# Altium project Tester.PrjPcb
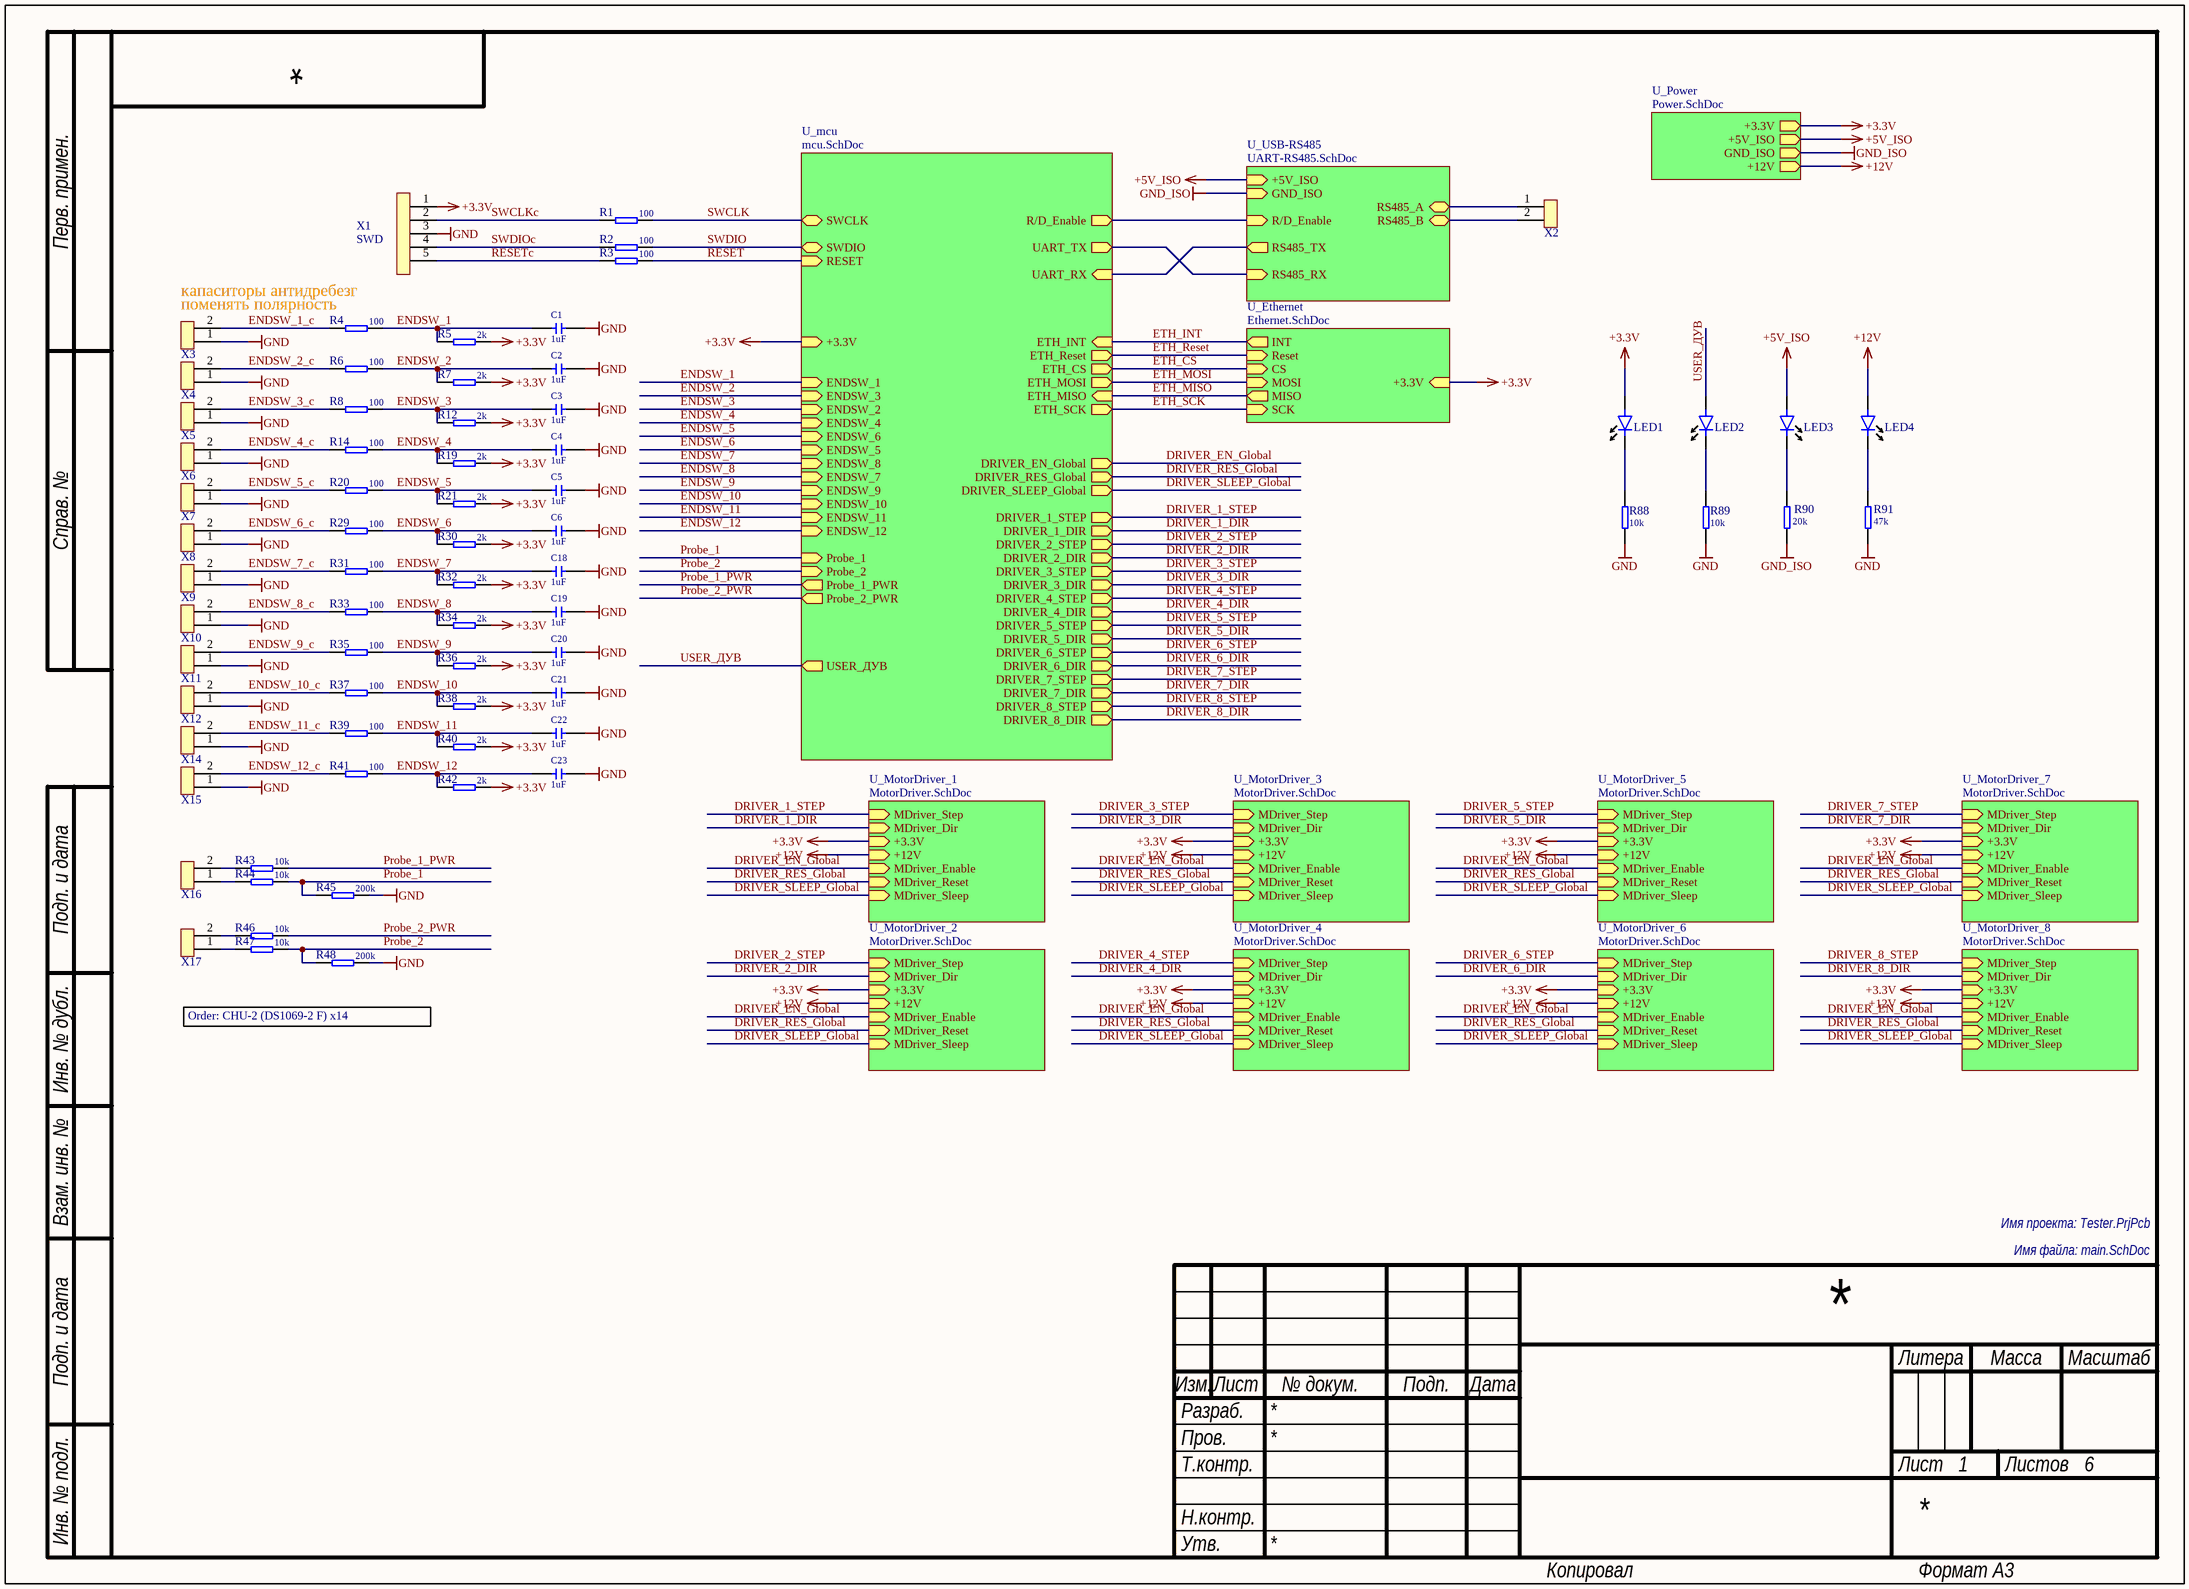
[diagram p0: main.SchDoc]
6 sheets, 275 parts. Net scope: hierarchical (ports join the sheet entries above them; power ports are global).
Sheets:
  main.SchDoc
    U_mcu = mcu.SchDoc
    U_Ethernet = Ethernet.SchDoc
    U_USB-RS485 = UART-RS485.SchDoc
    U_MotorDriver_1 = MotorDriver.SchDoc
    U_Power = Power.SchDoc
    U_MotorDriver_2 = MotorDriver.SchDoc
    U_MotorDriver_3 = MotorDriver.SchDoc
    U_MotorDriver_4 = MotorDriver.SchDoc
    U_MotorDriver_5 = MotorDriver.SchDoc
    U_MotorDriver_6 = MotorDriver.SchDoc
    U_MotorDriver_7 = MotorDriver.SchDoc
    U_MotorDriver_8 = MotorDriver.SchDoc

## Sheet main.SchDoc
size 410 x 297 mm; SheetNumber: 1; SheetTotal: 6

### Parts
Additional_order2  Order: CHU-2 (DS1069-2 F) x14  (hidden comment: Additional order)  (mechanical)
C1  1uF  [CERCAP 0603]
C2  1uF  [CERCAP 0603]
C3  1uF  [CERCAP 0603]
C4  1uF  [CERCAP 0603]
C5  1uF  [CERCAP 0603]
C6  1uF  [CERCAP 0603]
C18  1uF  [CERCAP 0603]
C19  1uF  [CERCAP 0603]
C20  1uF  [CERCAP 0603]
C21  1uF  [CERCAP 0603]
C22  1uF  [CERCAP 0603]
C23  1uF  [CERCAP 0603]
LED1  LED  [LED-0603N]  (value not drawn)
LED2  LED  [LED-0603N]  (value not drawn)
LED3  ***LED WHITE***  [LED-0603N]  (value not drawn)
LED4  ***LED WHITE***  [LED-0603N]  (value not drawn)
R1  100  [RES 0603]
R2  100  [RES 0603]
R3  100  [RES 0603]
R4  100  [RES 0603]
R5  2k  [RES 0603]
R6  100  [RES 0603]
R7  2k  [RES 0603]
R8  100  [RES 0603]
R12  2k  [RES 0603]
R14  100  [RES 0603]
R19  2k  [RES 0603]
R20  100  [RES 0603]
R21  2k  [RES 0603]
R29  100  [RES 0603]
R30  2k  [RES 0603]
R31  100  [RES 0603]
R32  2k  [RES 0603]
R33  100  [RES 0603]
R34  2k  [RES 0603]
R35  100  [RES 0603]
R36  2k  [RES 0603]
R37  100  [RES 0603]
R38  2k  [RES 0603]
R39  100  [RES 0603]
R40  2k  [RES 0603]
R41  100  [RES 0603]
R42  2k  [RES 0603]
R43  10k  [RES 0603]
R44  10k  [RES 0603]
R45  200k  [RES 0603]
R46  10k  [RES 0603]
R47  10k  [RES 0603]
R48  200k  [RES 0603]
R88  10k  [RES 0603]
R89  10k  [RES 0603]
R90  value 20k  [RES 0603]
R91  value 47k  [RES 0603]
X1  SWD  [PLS-5-2.54]
X2  Header  [CWF-2]  (value not drawn)
X3  Header  [CWF-2]  (value not drawn)
X4  Header  [CWF-2]  (value not drawn)
X5  Header  [CWF-2]  (value not drawn)
X6  Header  [CWF-2]  (value not drawn)
X7  Header  [CWF-2]  (value not drawn)
X8  Header  [CWF-2]  (value not drawn)
X9  Header  [CWF-2]  (value not drawn)
X10  Header  [CWF-2]  (value not drawn)
X11  Header  [CWF-2]  (value not drawn)
X12  Header  [CWF-2]  (value not drawn)
X14  Header  [CWF-2]  (value not drawn)
X15  Header  [CWF-2]  (value not drawn)
X16  Header  [CWF-2]  (value not drawn)
X17  Header  [CWF-2]  (value not drawn)

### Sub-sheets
U_Ethernet = Ethernet.SchDoc: +3.3V (in), Reset (in), CS (in), MOSI (in), MISO (out), SCK (in), INT (out)
U_mcu = mcu.SchDoc: UART_TX (out), UART_RX (in), SWCLK (bidir), SWDIO (bidir), RESET (in), +3.3V (in), ETH_INT (in), ETH_Reset (out), ETH_CS (out), ETH_MOSI (out), ETH_MISO (in), ETH_SCK (out), ENDSW_1 (in), ENDSW_2 (in), ENDSW_3 (in), ENDSW_4 (in), ENDSW_5 (in), ENDSW_6 (in), ENDSW_7 (in), ENDSW_8 (in), ENDSW_9 (in), ENDSW_10 (in), R/D_Enable (out), ENDSW_11 (in), ENDSW_12 (in), Probe_1 (in), Probe_2 (in), DRIVER_EN_Global (out), DRIVER_RES_Global (out), DRIVER_SLEEP_Global (out), DRIVER_1_STEP (out), DRIVER_1_DIR (out), DRIVER_2_STEP (out), DRIVER_2_DIR (out), DRIVER_3_STEP (out), DRIVER_3_DIR (out), DRIVER_4_STEP (out), DRIVER_4_DIR (out), DRIVER_5_STEP (out), DRIVER_5_DIR (out), DRIVER_6_STEP (out), DRIVER_6_DIR (out), DRIVER_7_STEP (out), DRIVER_7_DIR (out), DRIVER_8_STEP (out), DRIVER_8_DIR (out), Probe_1_PWR (out), Probe_2_PWR (out), USER_ДУВ (out)
U_MotorDriver_1 = MotorDriver.SchDoc: MDriver_Step (in), MDriver_Dir (in), +3.3V (in), +12V (in), MDriver_Enable (in), MDriver_Reset (in), MDriver_Sleep (in)
U_MotorDriver_2 = MotorDriver.SchDoc: MDriver_Step (in), MDriver_Dir (in), +3.3V (in), +12V (in), MDriver_Enable (in), MDriver_Reset (in), MDriver_Sleep (in)
U_MotorDriver_3 = MotorDriver.SchDoc: MDriver_Step (in), MDriver_Dir (in), +3.3V (in), +12V (in), MDriver_Enable (in), MDriver_Reset (in), MDriver_Sleep (in)
U_MotorDriver_4 = MotorDriver.SchDoc: MDriver_Step (in), MDriver_Dir (in), +3.3V (in), +12V (in), MDriver_Enable (in), MDriver_Reset (in), MDriver_Sleep (in)
U_MotorDriver_5 = MotorDriver.SchDoc: MDriver_Step (in), MDriver_Dir (in), +3.3V (in), +12V (in), MDriver_Enable (in), MDriver_Reset (in), MDriver_Sleep (in)
U_MotorDriver_6 = MotorDriver.SchDoc: MDriver_Step (in), MDriver_Dir (in), +3.3V (in), +12V (in), MDriver_Enable (in), MDriver_Reset (in), MDriver_Sleep (in)
U_MotorDriver_7 = MotorDriver.SchDoc: MDriver_Step (in), MDriver_Dir (in), +3.3V (in), +12V (in), MDriver_Enable (in), MDriver_Reset (in), MDriver_Sleep (in)
U_MotorDriver_8 = MotorDriver.SchDoc: MDriver_Step (in), MDriver_Dir (in), +3.3V (in), +12V (in), MDriver_Enable (in), MDriver_Reset (in), MDriver_Sleep (in)
U_Power = Power.SchDoc: +5V_ISO (out), GND_ISO (out), +12V (out), +3.3V (out)
U_USB-RS485 = UART-RS485.SchDoc: RS485_RX (in), RS485_TX (out), GND_ISO (in), +5V_ISO (in), R/D_Enable (in), RS485_A (bidir), RS485_B (bidir)

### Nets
+3.3V: LED1.1(Anode) R5.2 R7.2 R12.2 R19.2 R21.2 R30.2 R32.2 R34.2 R36.2 R38.2 R40.2 R42.2 X1.1 ; sheet U_mcu/+3.3V, sheet U_Ethernet/+3.3V, sheet U_MotorDriver_1/+3.3V, sheet U_Power/+3.3V, sheet U_MotorDriver_2/+3.3V, sheet U_MotorDriver_3/+3.3V, sheet U_MotorDriver_4/+3.3V, sheet U_MotorDriver_5/+3.3V, sheet U_MotorDriver_6/+3.3V, sheet U_MotorDriver_7/+3.3V, sheet U_MotorDriver_8/+3.3V
+5V_ISO: LED3.1(Anode) ; sheet U_USB-RS485/+5V_ISO, sheet U_Power/+5V_ISO
+12V: LED4.1(Anode) ; sheet U_MotorDriver_1/+12V, sheet U_Power/+12V, sheet U_MotorDriver_2/+12V, sheet U_MotorDriver_3/+12V, sheet U_MotorDriver_4/+12V, sheet U_MotorDriver_5/+12V, sheet U_MotorDriver_6/+12V, sheet U_MotorDriver_7/+12V, sheet U_MotorDriver_8/+12V
GND: C1.2 C2.2 C3.2 C4.2 C5.2 C6.2 C18.2 C19.2 C20.2 C21.2 C22.2 C23.2 R45.2 R48.2 R88.2 R89.2 R91.2 X1.3 X3.1 X4.1 X5.1 X6.1 X7.1 X8.1 X9.1 X10.1 X11.1 X12.1 X14.1 X15.1
GND_ISO: R90.2 ; sheet U_USB-RS485/GND_ISO, sheet U_Power/GND_ISO
DRIVER_1_DIR: sheet U_mcu/DRIVER_1_DIR, sheet U_MotorDriver_1/MDriver_Dir
DRIVER_1_STEP: sheet U_mcu/DRIVER_1_STEP, sheet U_MotorDriver_1/MDriver_Step
DRIVER_2_DIR: sheet U_mcu/DRIVER_2_DIR, sheet U_MotorDriver_2/MDriver_Dir
DRIVER_2_STEP: sheet U_mcu/DRIVER_2_STEP, sheet U_MotorDriver_2/MDriver_Step
DRIVER_3_DIR: sheet U_mcu/DRIVER_3_DIR, sheet U_MotorDriver_3/MDriver_Dir
DRIVER_3_STEP: sheet U_mcu/DRIVER_3_STEP, sheet U_MotorDriver_3/MDriver_Step
DRIVER_4_DIR: sheet U_mcu/DRIVER_4_DIR, sheet U_MotorDriver_4/MDriver_Dir
DRIVER_4_STEP: sheet U_mcu/DRIVER_4_STEP, sheet U_MotorDriver_4/MDriver_Step
DRIVER_5_DIR: sheet U_mcu/DRIVER_5_DIR, sheet U_MotorDriver_5/MDriver_Dir
DRIVER_5_STEP: sheet U_mcu/DRIVER_5_STEP, sheet U_MotorDriver_5/MDriver_Step
DRIVER_6_DIR: sheet U_mcu/DRIVER_6_DIR, sheet U_MotorDriver_6/MDriver_Dir
DRIVER_6_STEP: sheet U_mcu/DRIVER_6_STEP, sheet U_MotorDriver_6/MDriver_Step
DRIVER_7_DIR: sheet U_mcu/DRIVER_7_DIR, sheet U_MotorDriver_7/MDriver_Dir
DRIVER_7_STEP: sheet U_mcu/DRIVER_7_STEP, sheet U_MotorDriver_7/MDriver_Step
DRIVER_8_DIR: sheet U_mcu/DRIVER_8_DIR, sheet U_MotorDriver_8/MDriver_Dir
DRIVER_8_STEP: sheet U_mcu/DRIVER_8_STEP, sheet U_MotorDriver_8/MDriver_Step
DRIVER_EN_Global: sheet U_mcu/DRIVER_EN_Global, sheet U_MotorDriver_1/MDriver_Enable, sheet U_MotorDriver_2/MDriver_Enable, sheet U_MotorDriver_3/MDriver_Enable, sheet U_MotorDriver_4/MDriver_Enable, sheet U_MotorDriver_5/MDriver_Enable, sheet U_MotorDriver_6/MDriver_Enable, sheet U_MotorDriver_7/MDriver_Enable, sheet U_MotorDriver_8/MDriver_Enable
DRIVER_RES_Global: sheet U_mcu/DRIVER_RES_Global, sheet U_MotorDriver_1/MDriver_Reset, sheet U_MotorDriver_2/MDriver_Reset, sheet U_MotorDriver_3/MDriver_Reset, sheet U_MotorDriver_4/MDriver_Reset, sheet U_MotorDriver_5/MDriver_Reset, sheet U_MotorDriver_6/MDriver_Reset, sheet U_MotorDriver_7/MDriver_Reset, sheet U_MotorDriver_8/MDriver_Reset
DRIVER_SLEEP_Global: sheet U_mcu/DRIVER_SLEEP_Global, sheet U_MotorDriver_1/MDriver_Sleep, sheet U_MotorDriver_2/MDriver_Sleep, sheet U_MotorDriver_3/MDriver_Sleep, sheet U_MotorDriver_4/MDriver_Sleep, sheet U_MotorDriver_5/MDriver_Sleep, sheet U_MotorDriver_6/MDriver_Sleep, sheet U_MotorDriver_7/MDriver_Sleep, sheet U_MotorDriver_8/MDriver_Sleep
ENDSW_1: C1.1 R4.2 R5.1 ; sheet U_mcu/ENDSW_1
ENDSW_1_c: R4.1 X3.2
ENDSW_2: C2.1 R6.2 R7.1 ; sheet U_mcu/ENDSW_3
ENDSW_2_c: R6.1 X4.2
ENDSW_3: C3.1 R8.2 R12.1 ; sheet U_mcu/ENDSW_2
ENDSW_3_c: R8.1 X5.2
ENDSW_4: C4.1 R14.2 R19.1 ; sheet U_mcu/ENDSW_4
ENDSW_4_c: R14.1 X6.2
ENDSW_5: C5.1 R20.2 R21.1 ; sheet U_mcu/ENDSW_6
ENDSW_5_c: R20.1 X7.2
ENDSW_6: C6.1 R29.2 R30.1 ; sheet U_mcu/ENDSW_5
ENDSW_6_c: R29.1 X8.2
ENDSW_7: C18.1 R31.2 R32.1 ; sheet U_mcu/ENDSW_8
ENDSW_7_c: R31.1 X9.2
ENDSW_8: C19.1 R33.2 R34.1 ; sheet U_mcu/ENDSW_7
ENDSW_8_c: R33.1 X10.2
ENDSW_9: C20.1 R35.2 R36.1 ; sheet U_mcu/ENDSW_9
ENDSW_9_c: R35.1 X11.2
ENDSW_10: C21.1 R37.2 R38.1 ; sheet U_mcu/ENDSW_10
ENDSW_10_c: R37.1 X12.2
ENDSW_11: C22.1 R39.2 R40.1 ; sheet U_mcu/ENDSW_11
ENDSW_11_c: R39.1 X14.2
ENDSW_12: C23.1 R41.2 R42.1 ; sheet U_mcu/ENDSW_12
ENDSW_12_c: R41.1 X15.2
ETH_CS: sheet U_mcu/ETH_CS, sheet U_Ethernet/CS
ETH_INT: sheet U_mcu/ETH_INT, sheet U_Ethernet/INT
ETH_MISO: sheet U_mcu/ETH_MISO, sheet U_Ethernet/MISO
ETH_MOSI: sheet U_mcu/ETH_MOSI, sheet U_Ethernet/MOSI
ETH_Reset: sheet U_mcu/ETH_Reset, sheet U_Ethernet/Reset
ETH_SCK: sheet U_mcu/ETH_SCK, sheet U_Ethernet/SCK
Probe_1: R44.2 R45.1 ; sheet U_mcu/Probe_1
Probe_1_PWR: R43.2 ; sheet U_mcu/Probe_1_PWR
Probe_2: R47.2 R48.1 ; sheet U_mcu/Probe_2
Probe_2_PWR: R46.2 ; sheet U_mcu/Probe_2_PWR
RESET: R3.2 ; sheet U_mcu/RESET
RESETc: R3.1 X1.5
SWCLK: R1.2 ; sheet U_mcu/SWCLK
SWCLKc: R1.1 X1.2
SWDIO: R2.2 ; sheet U_mcu/SWDIO
SWDIOc: R2.1 X1.4
USER_ДУВ: LED2.1(Anode) ; sheet U_mcu/USER_ДУВ
NetIC1_25: sheet U_mcu/UART_TX, sheet U_USB-RS485/RS485_RX
NetIC1_26: sheet U_mcu/UART_RX, sheet U_USB-RS485/RS485_TX
NetIC1_27: sheet U_mcu/R/D_Enable, sheet U_USB-RS485/R/D_Enable
NetLED1_2: LED1.2(Cathode) R88.1
NetLED2_2: LED2.2(Cathode) R89.1
NetLED3_2: LED3.2(Cathode) R90.1
NetLED4_2: LED4.2(Cathode) R91.1
NetR43_1: R43.1 X16.2
NetR44_1: R44.1 X16.1
NetR46_1: R46.1 X17.2
NetR47_1: R47.1 X17.1
NetR69_1: X2.2 ; sheet U_USB-RS485/RS485_B
NetR69_2: X2.1 ; sheet U_USB-RS485/RS485_A

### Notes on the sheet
- поменять полярность
- капаситоры антидребезг

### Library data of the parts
Additional_order2 = Additional_Order
C1-C6 C18-C23 = cap: Capacitor; Voltage: *V; Dielectric: *X5R; Tolerance: *%; OrderAdvanced: CERCAP *0603 1uF *X5R *%
LED1 LED2 = LED: Light Emittering Diode; PartValue: LED*0603 *; Order: LED 0603 Red; OriginalSource: AltTab
LED3 LED4 = LED: Light Emittering Diode; PartValue: LED*0603 *; OriginalSource: AltTab
R1-R4 R6 R8 R14 R20 R29 R31 R33 R35 R37 R39 R41 = Resistor: OrderAdvanced: RES *0603 100 *%; Tolerance: *%
R5 R7 R12 R19 R21 R30 R32 R34 R36 R38 R40 R42 = Resistor: OrderAdvanced: RES *0603 2k *%; Tolerance: *%
R43 R44 R46 R47 R88 R89 = Resistor: OrderAdvanced: RES *0603 10k *%; Tolerance: *%
R45 R48 = Resistor: OrderAdvanced: RES *0603 200k *%; Tolerance: *%
R90 = Resistor: OrderAdvanced: RES *0603 20k *%; Tolerance: *%
R91 = Resistor: OrderAdvanced: RES *0603 47k *%; Tolerance: *%
X1 = Header 5x1: 5x1 header; Order: 2.54 horizontal 5 contacts SMD; System: Connector; OriginalSource: AltTab
X2 = Header 2x1: 2x1 header; System: Connector; OriginalSource: AltTab
X3-X12 X14-X17 = Header 2x1: 2x1 header; Order: CWF-2 (DS1069-2 M); System: Connector; OriginalSource: AltTab

## Sheet mcu.SchDoc
size A4; SheetNumber: 2; SheetTotal: 6
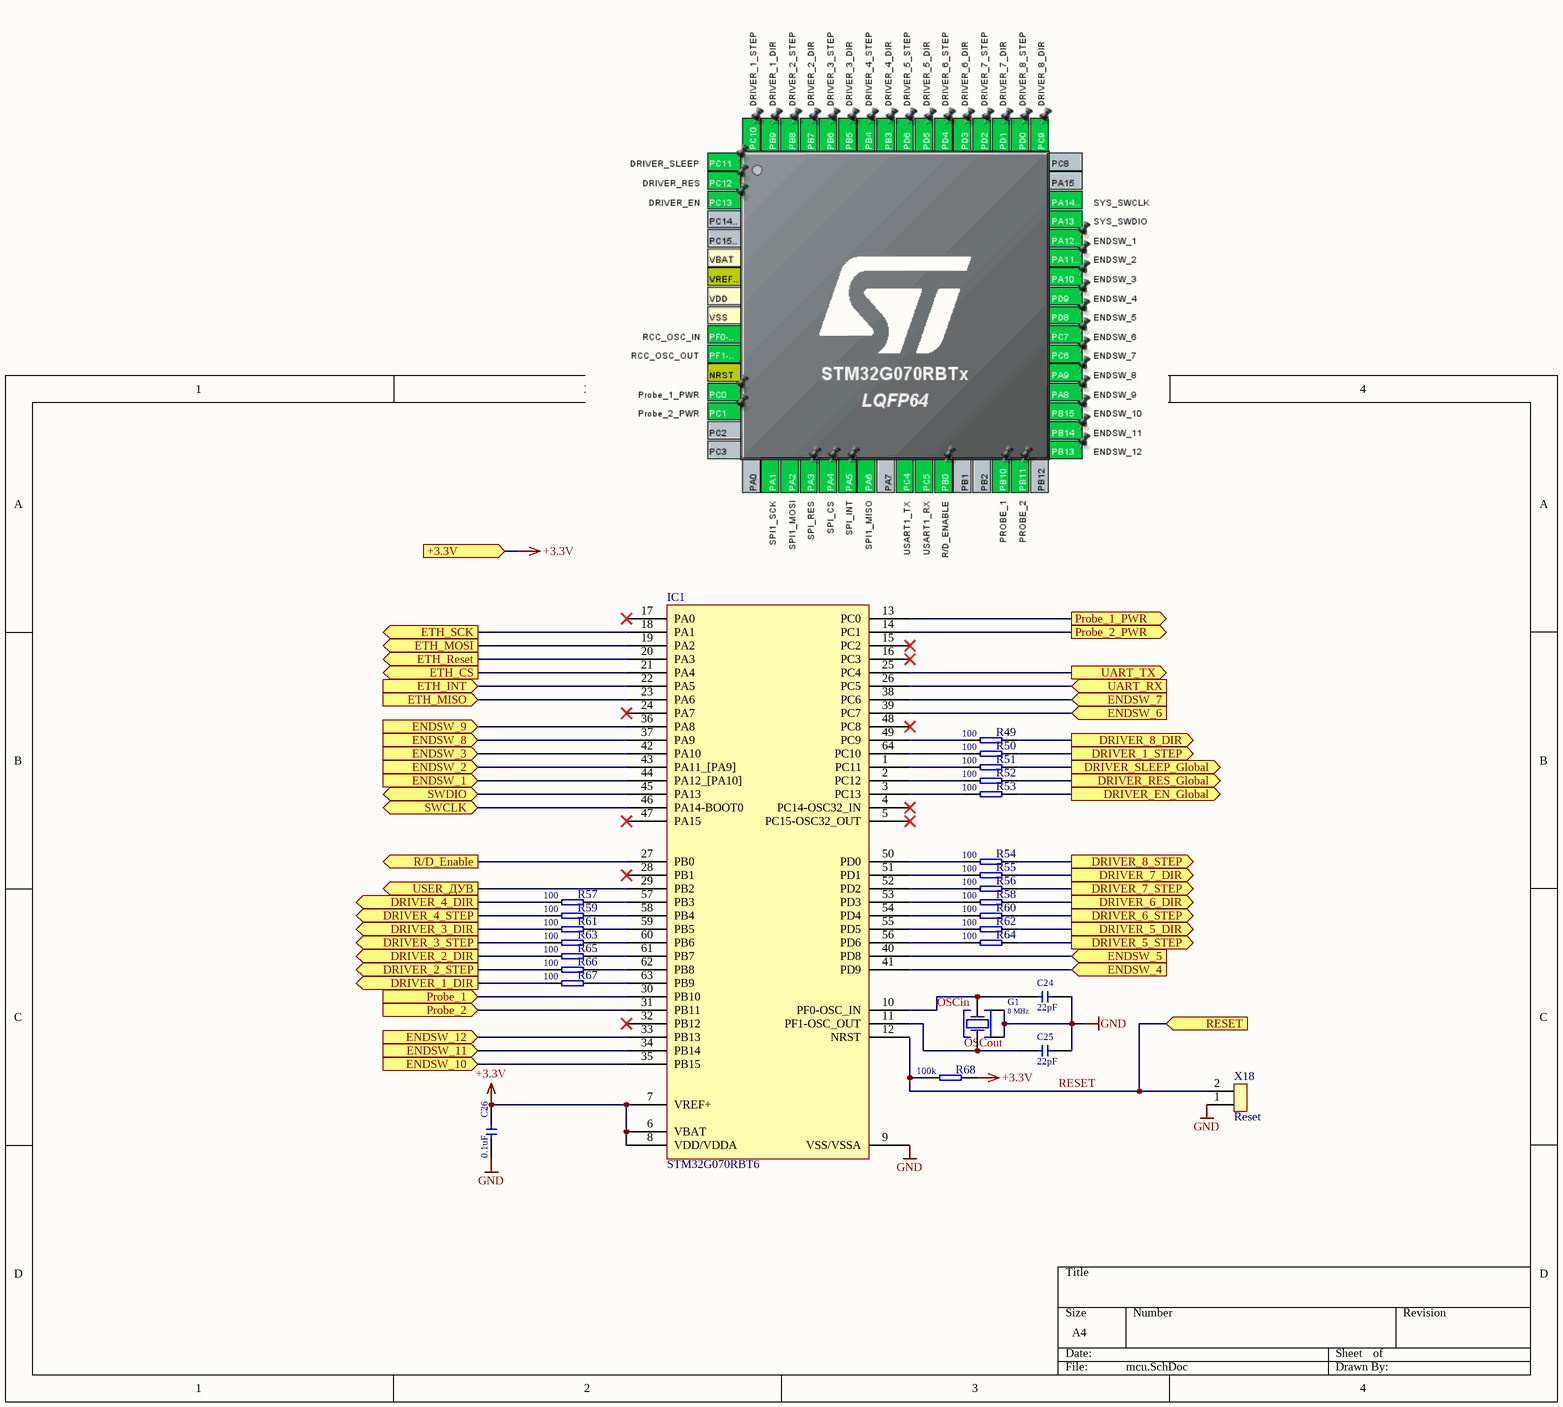
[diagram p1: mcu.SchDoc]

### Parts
C24  22pF  [CERCAP 0603]
C25  22pF  [CERCAP 0603]
C26  0.1uF  [CERCAP 0603]
G1  Frequency: 8 MHz  [SMD_3225_4N]  (hidden comment: Crystal-4)
IC1  STM32G070RBT6  [LQFP-64]
R49  100  [RES-0603N]
R50  100  [RES-0603N]
R51  100  [RES-0603N]
R52  100  [RES-0603N]
R53  100  [RES-0603N]
R54  100  [RES-0603N]
R55  100  [RES-0603N]
R56  100  [RES-0603N]
R57  100  [RES-0603N]
R58  100  [RES-0603N]
R59  100  [RES-0603N]
R60  100  [RES-0603N]
R61  100  [RES-0603N]
R62  100  [RES-0603N]
R63  100  [RES-0603N]
R64  100  [RES-0603N]
R65  100  [RES-0603N]
R66  100  [RES-0603N]
R67  100  [RES-0603N]
R68  100k  [RES-0603N]
X18  Reset  [PLL-2-1.27]

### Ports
+3.3V (in, see main[2A], Ethernet[2A], MotorDriver[3B], Power[3C]), DRIVER_1_DIR (out, see main[3A]), DRIVER_1_STEP (out, see main[3A]), DRIVER_2_DIR (out, see main[3A]), DRIVER_2_STEP (out, see main[3A]), DRIVER_3_DIR (out, see main[3A]), DRIVER_3_STEP (out, see main[3A]), DRIVER_4_DIR (out, see main[3A]), DRIVER_4_STEP (out, see main[3A]), DRIVER_5_DIR (out, see main[3A]), DRIVER_5_STEP (out, see main[3A]), DRIVER_6_DIR (out, see main[3A]), DRIVER_6_STEP (out, see main[3A]), DRIVER_7_DIR (out, see main[3A]), DRIVER_7_STEP (out, see main[3A]), DRIVER_8_DIR (out, see main[3A]), DRIVER_8_STEP (out, see main[3A]), DRIVER_EN_Global (out, see main[3A]), DRIVER_RES_Global (out, see main[3A]), DRIVER_SLEEP_Global (out, see main[3A]), ENDSW_1 (in, see main[2A]), ENDSW_2 (in, see main[2A]), ENDSW_3 (in, see main[2A]), ENDSW_4 (in, see main[2A]), ENDSW_5 (in, see main[2A]), ENDSW_6 (in, see main[2A]), ENDSW_7 (in, see main[2A]), ENDSW_8 (in, see main[2A]), ENDSW_9 (in, see main[2A]), ENDSW_10 (in, see main[2A]), ENDSW_11 (in, see main[2A]), ENDSW_12 (in, see main[2A]), ETH_CS (out, see main[3A]), ETH_INT (in, see main[3A]), ETH_MISO (in, see main[3A]), ETH_MOSI (out, see main[3A]), ETH_Reset (out, see main[3A]), ETH_SCK (out, see main[3A]), Probe_1 (in, see main[2A]), Probe_1_PWR (out, see main[2A]), Probe_2 (in, see main[2A]), Probe_2_PWR (out, see main[2A]), R/D_Enable (out, see main[3A], UART-RS485[2B]), RESET (in, see main[2A]), SWCLK (bidir, see main[2A]), SWDIO (bidir, see main[2A]), UART_RX (in, see main[3A]), UART_TX (out, see main[3A]), USER_ДУВ (out, see main[2A])

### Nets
+3.3V: C26.2 IC1.6(VBAT) IC1.7(VREF+) IC1.8(VDD/VDDA) R68.1 ; port +3.3V
GND: C24.1 C25.1 C26.1 G1.2 G1.4 IC1.9(VSS/VSSA) X18.1
DRIVER_1_DIR: R67.2 ; port DRIVER_1_DIR
DRIVER_1_STEP: R50.1 ; port DRIVER_1_STEP
DRIVER_2_DIR: R65.2 ; port DRIVER_2_DIR
DRIVER_2_STEP: R66.2 ; port DRIVER_2_STEP
DRIVER_3_DIR: R61.2 ; port DRIVER_3_DIR
DRIVER_3_STEP: R63.2 ; port DRIVER_3_STEP
DRIVER_4_DIR: R57.2 ; port DRIVER_4_DIR
DRIVER_4_STEP: R59.2 ; port DRIVER_4_STEP
DRIVER_5_DIR: R62.1 ; port DRIVER_5_DIR
DRIVER_5_STEP: R64.1 ; port DRIVER_5_STEP
DRIVER_6_DIR: R58.1 ; port DRIVER_6_DIR
DRIVER_6_STEP: R60.1 ; port DRIVER_6_STEP
DRIVER_7_DIR: R55.1 ; port DRIVER_7_DIR
DRIVER_7_STEP: R56.1 ; port DRIVER_7_STEP
DRIVER_8_DIR: R49.1 ; port DRIVER_8_DIR
DRIVER_8_STEP: R54.1 ; port DRIVER_8_STEP
DRIVER_EN_Global: R53.1 ; port DRIVER_EN_Global
DRIVER_RES_Global: R52.1 ; port DRIVER_RES_Global
DRIVER_SLEEP_Global: R51.1 ; port DRIVER_SLEEP_Global
ENDSW_1: IC1.44(PA12_[PA10]) ; port ENDSW_1
ENDSW_2: IC1.42(PA10) ; port ENDSW_3
ENDSW_3: IC1.43(PA11_[PA9]) ; port ENDSW_2
ENDSW_4: IC1.41(PD9) ; port ENDSW_4
ENDSW_5: IC1.39(PC7) ; port ENDSW_6
ENDSW_6: IC1.40(PD8) ; port ENDSW_5
ENDSW_7: IC1.37(PA9) ; port ENDSW_8
ENDSW_8: IC1.38(PC6) ; port ENDSW_7
ENDSW_9: IC1.36(PA8) ; port ENDSW_9
ENDSW_10: IC1.35(PB15) ; port ENDSW_10
ENDSW_11: IC1.34(PB14) ; port ENDSW_11
ENDSW_12: IC1.33(PB13) ; port ENDSW_12
ETH_CS: IC1.21(PA4) ; port ETH_CS
ETH_INT: IC1.22(PA5) ; port ETH_INT
ETH_MISO: IC1.23(PA6) ; port ETH_MISO
ETH_MOSI: IC1.19(PA2) ; port ETH_MOSI
ETH_Reset: IC1.20(PA3) ; port ETH_Reset
ETH_SCK: IC1.18(PA1) ; port ETH_SCK
OSCin: C24.2 G1.1 IC1.10(PF0-OSC_IN)
OSCout: C25.2 G1.3 IC1.11(PF1-OSC_OUT)
Probe_1: IC1.30(PB10) ; port Probe_1
Probe_1_PWR: IC1.13(PC0) ; port Probe_1_PWR
Probe_2: IC1.31(PB11) ; port Probe_2
Probe_2_PWR: IC1.14(PC1) ; port Probe_2_PWR
RESET: IC1.12(NRST) R68.2 X18.2 ; port RESET
SWCLK: IC1.46(PA14-BOOT0) ; port SWCLK
SWDIO: IC1.45(PA13) ; port SWDIO
USER_ДУВ: IC1.29(PB2) ; port USER_ДУВ
NetIC1_1: IC1.1(PC11) R51.2
NetIC1_2: IC1.2(PC12) R52.2
NetIC1_3: IC1.3(PC13) R53.2
NetIC1_25: IC1.25(PC4) ; port UART_TX
NetIC1_26: IC1.26(PC5) ; port UART_RX
NetIC1_27: IC1.27(PB0) ; port R/D_Enable
NetIC1_49: IC1.49(PC9) R49.2
NetIC1_50: IC1.50(PD0) R54.2
NetIC1_51: IC1.51(PD1) R55.2
NetIC1_52: IC1.52(PD2) R56.2
NetIC1_53: IC1.53(PD3) R58.2
NetIC1_54: IC1.54(PD4) R60.2
NetIC1_55: IC1.55(PD5) R62.2
NetIC1_56: IC1.56(PD6) R64.2
NetIC1_57: IC1.57(PB3) R57.1
NetIC1_58: IC1.58(PB4) R59.1
NetIC1_59: IC1.59(PB5) R61.1
NetIC1_60: IC1.60(PB6) R63.1
NetIC1_61: IC1.61(PB7) R65.1
NetIC1_62: IC1.62(PB8) R66.1
NetIC1_63: IC1.63(PB9) R67.1
NetIC1_64: IC1.64(PC10) R50.2

Not connected (* = marked no-connect by the designer): IC1 4(PC14-OSC32_IN)* 5(PC15-OSC32_OUT)* 15(PC2)* 16(PC3)* 17(PA0)* 24(PA7)* 28(PB1)* 32(PB12)* 47(PA15)* 48(PC8)*

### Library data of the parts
C24 C25 = cap: Capacitor; Voltage: 10V; Dielectric: *X5R; Tolerance: *%; OrderAdvanced: CERCAP *0603 22pF *X5R *%
C26 = cap: Capacitor; Voltage: 16V; Dielectric: *X5R; Tolerance: *%; OrderAdvanced: CERCAP *0603 0.1uF *X5R *%
G1 = Crystal-4: Quartz Crystal Resonator; Order: *3225 8MHz crystal*; Load Capacitance (CL): * pF; Equivalent Resistance: * Ohms; Stability over operation temperance: * ppm
IC1 = STM32G070RBT6TR_1: Integrated Circuit
R49-R67 = Resistor: as R1 on sheet main
R68 = Resistor: OrderAdvanced: RES *0603 100k *%; Tolerance: *%
X18 = Header 2x1: 2x1 header; Order: pll-1.27-2

## Sheet Ethernet.SchDoc
size 410 x 297 mm; SheetNumber: 3; SheetTotal: 6; PageSetup: Record=PageOptions¦CenterHorizontal=True¦CenterVertical=True¦PrintScale=1.00¦XCorrection=1.00¦YCorrection=1.00¦PrintKind=1¦BorderSize=5000000¦LeftOffset=0¦BottomOffset=0¦Orientation=2¦PaperLength=1000¦PaperWidth=1000¦Scale=100¦PaperSource=15¦PrintQuality=1200¦MediaType=1¦DitherType=10¦PaperKind=A3¦PrintScaleMode=1; Weight: -; ScaleFactor: -; NormInspection: Норм.Контр.
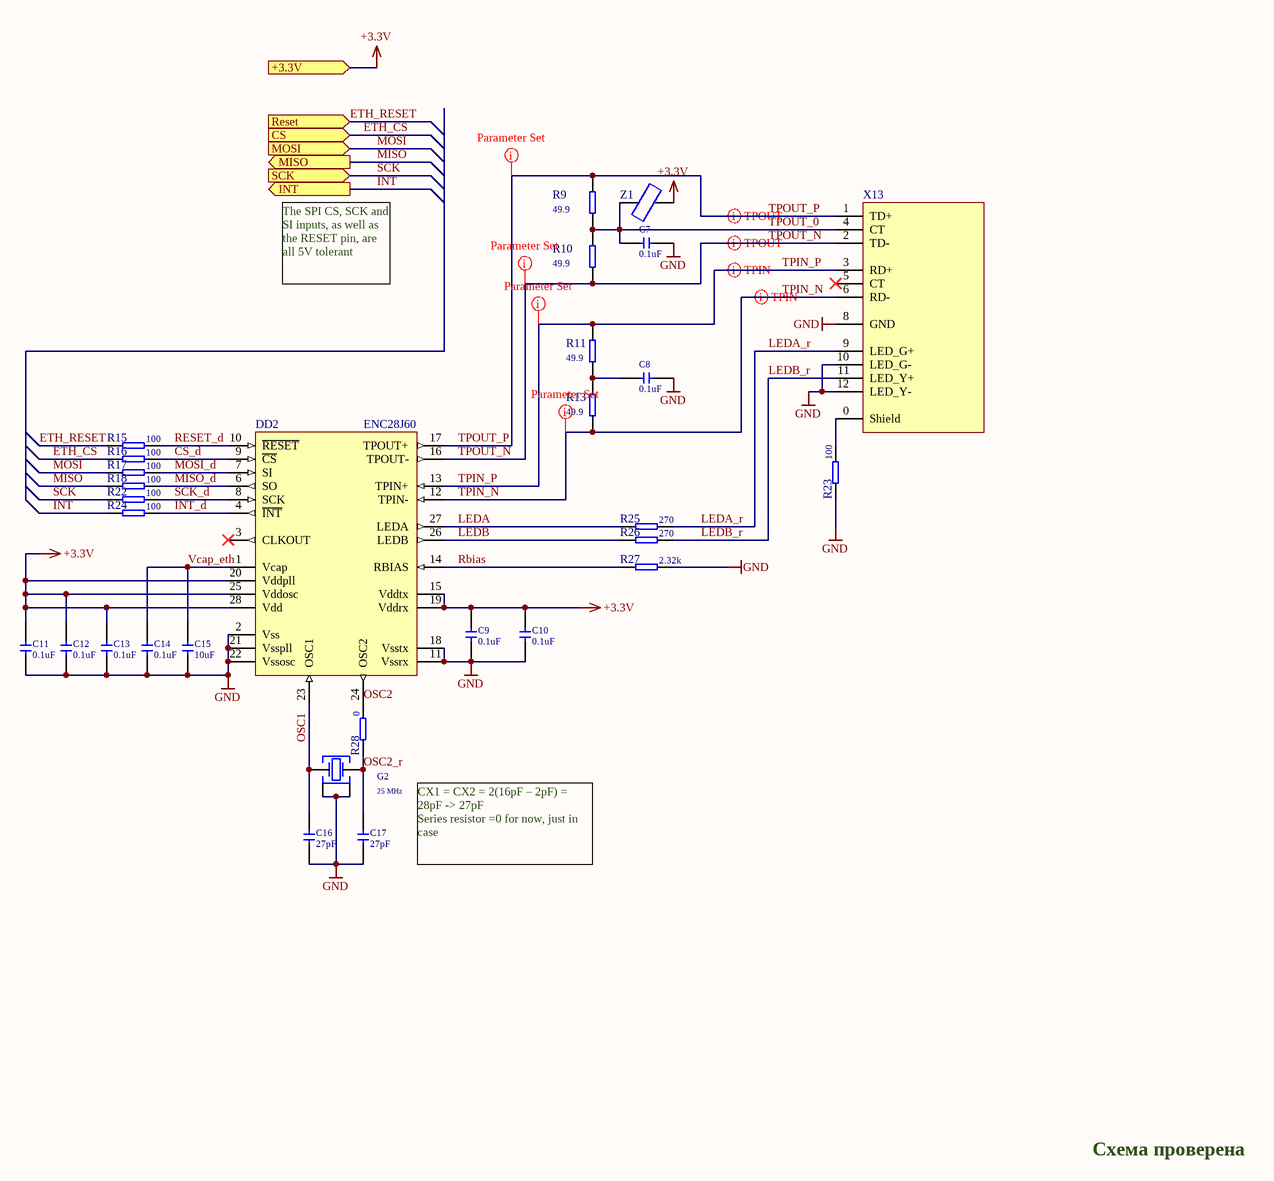
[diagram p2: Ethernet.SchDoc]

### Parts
C7  0.1uF  [CERCAP 0603]
C8  0.1uF  [CERCAP 0603]
C9  0.1uF  [CERCAP 0603]
C10  0.1uF  [CERCAP 0603]
C11  0.1uF  [CERCAP 0603]
C12  0.1uF  [CERCAP 0603]
C13  0.1uF  [CERCAP 0603]
C14  0.1uF  [CERCAP 0603]
C15  10uF  [CERCAP 0603]
C16  27pF  [CERCAP 0603]
C17  27pF  [CERCAP 0603]
DD2  ENC28J60  [SSOP-28]
G2  Frequency: 25 MHz  [SMD_3225_4N]  (hidden comment: Crystal-4)
R9  49.9  [RES 0603]
R10  49.9  [RES 0603]
R11  49.9  [RES 0603]
R13  49.9  [RES 0603]
R15  100  [RES 0603]
R16  100  [RES 0603]
R17  100  [RES 0603]
R18  100  [RES 0603]
R22  100  [RES 0603]
R23  100  [RES 0603]
R24  100  [RES 0603]
R25  270  [RES 0603]
R26  270  [RES 0603]
R27  2.32k  [RES 0603]
R28  0  [RES 0603]
X13  Ethernet  [KLS12-TL058N]  (value not drawn)
Z1  Bead  [CHIP-0603]  (value not drawn)

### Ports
+3.3V (in, see main[3A], mcu[2A], MotorDriver[3B], Power[3C]), CS (in, see main[3A]), INT (out, see main[3A]), MISO (out, see main[3A]), MOSI (in, see main[3A]), Reset (in, see main[3A]), SCK (in, see main[3A])

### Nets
+3.3V: C9.2 C10.2 C11.2 C12.2 C13.2 DD2.15(Vddtx) DD2.19(Vddrx) DD2.20(Vddpll) DD2.25(Vddosc) DD2.28(Vdd) Z1.2 ; port +3.3V
GND: C7.1 C8.1 C9.1 C10.1 C11.1 C12.1 C13.1 C14.1 C15.1 C16.1 C17.1 DD2.2(Vss) DD2.11(Vssrx) DD2.18(Vsstx) DD2.21(Vsspll) DD2.22(Vssosc) G2.2 G2.4 R23.1 R27.2 X13.8(GND) X13.10(LED_G-) X13.12(LED_Y-)
CS_d: DD2.9(~{CS}) R16.2
ETH_CS: R16.1 ; port CS
ETH_Reset: R15.1 ; port Reset
INT: R24.1 ; port INT  [project net ETH_INT]
INT_d: DD2.4(~{INT}) R24.2
LEDA: DD2.27(LEDA) R25.1
LEDA_r: R25.2 X13.9(LED_G+)
LEDB: DD2.26(LEDB) R26.1
LEDB_r: R26.2 X13.11(LED_Y+)
MISO: R18.1 ; port MISO  [project net ETH_MISO]
MISO_d: DD2.6(SO) R18.2
MOSI: R17.1 ; port MOSI  [project net ETH_MOSI]
MOSI_d: DD2.7(SI) R17.2
OSC1: C16.2 DD2.23(OSC1) G2.1
OSC2: DD2.24(OSC2) R28.2
OSC2_r: C17.2 G2.3 R28.1
Rbias: DD2.14(RBIAS) R27.1
RESET_d: DD2.10(~{RESET}) R15.2
SCK: R22.1 ; port SCK  [project net ETH_SCK]
SCK_d: DD2.8(SCK) R22.2
TPIN_N: DD2.12(TPIN-) R13.2 X13.6(RD-)
TPIN_P: DD2.13(TPIN+) R11.2 X13.3(RD+)
TPOUT_0: C7.2 R9.1 R10.1 X13.4(CT) Z1.1
TPOUT_N: DD2.16(TPOUT-) R10.2 X13.2(TD-)
TPOUT_P: DD2.17(TPOUT+) R9.2 X13.1(TD+)
Vcap_eth: C14.2 C15.2 DD2.1(Vcap)
NetC8_2: C8.2 R11.1 R13.1
NetR23_2: R23.2 X13.0(Shield)

Not connected (* = marked no-connect by the designer): DD2 3(CLKOUT)*; X13 5(CT)*

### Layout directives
differential pair: TPIN_N, TPIN_P, TPOUT_N, TPOUT_P
net class Ethernet; rule Matched Net Lengths [Tolerance = 2mm]: TPIN_N, TPIN_P, TPOUT_N, TPOUT_P

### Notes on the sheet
- The SPI CS, SCK and SI inputs, as well as the RESET pin, are all 5V tolerant
- CX1 = CX2 = 2(16pF – 2pF) = 28pF -> 27pF
  Series resistor =0 for now, just in case
- Схема проверена

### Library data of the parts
C7-C14 = cap: Capacitor; Voltage: 10V; Dielectric: *X5R; Tolerance: *%; OrderAdvanced: CERCAP *0603 0.1uF *X5R *%
C15 = cap: Capacitor; Voltage: 10V; Dielectric: *X5R; Tolerance: *%; OrderAdvanced: CERCAP *0603 10uF *X5R *%
C16 C17 = cap: Capacitor; Voltage: 10V; Dielectric: *X5R; Tolerance: *%; OrderAdvanced: CERCAP *0603 27pF *X5R *%
DD2 = ENC28J60: Stand-Alone Ethernet Controller with SPI Interface; Order: ENC28J60T-I/SS
G2 = Crystal-4: Quartz Crystal Resonator; Order: SJK-7U-25.000-16-20-40-C-100; Load Capacitance (CL): 16 pF; Shunt Capacitance (Co): * pF; Equivalent Resistance: * Ohms; Stability over operation temperance: * ppm
R9-R11 R13 = Resistor: OrderAdvanced: RES *0603 49.9 *%; Tolerance: *%
R15-R18 R22-R24 = Resistor: as R1 on sheet main
R25 R26 = Resistor: OrderAdvanced: RES *0603 270 *%; Tolerance: *%
R27 = Resistor: OrderAdvanced: RES *0603 2.32k *%; Tolerance: *%
R28 = Resistor: OrderAdvanced: RES *0603 0 *%; Tolerance: *%
X13 = RJ-45: RJ-45 with led and transformer
Z1 = Bead: Ferrite bead; Order: BLM18EG101TN1D

## Sheet UART-RS485.SchDoc
size A4; SheetNumber: 4; SheetTotal: 6
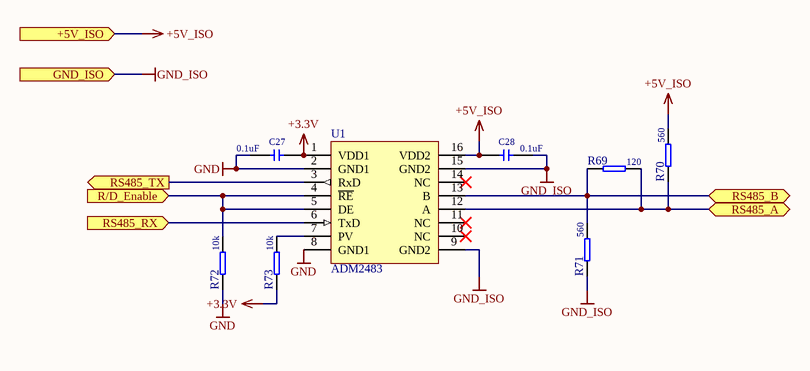
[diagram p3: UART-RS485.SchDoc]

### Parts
C27  0.1uF  [CERCAP 0603]
C28  0.1uF  [CERCAP 0603]
R69  120  [RES 0603]
R70  560  [RES 0603]
R71  560  [RES 0603]
R72  10k  [RES 0603]
R73  10k  [RES 0603]
U1  ADM2483  [SO-16_300mil]

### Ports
+5V_ISO (in, see main[3A], Power[4B]), GND_ISO (in, see main[3A], Power[4B]), R/D_Enable (in, see main[3A], mcu[1B]), RS485_A (bidir, see main[3A]), RS485_B (bidir, see main[3A]), RS485_RX (in, see main[3A]), RS485_TX (out, see main[3A])

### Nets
+3.3V: C27.2 R73.1 U1.1(VDD1)
+5V_ISO: C28.1 R70.2 U1.16(VDD2) ; port +5V_ISO
GND: C27.1 R72.1 U1.2(GND1) U1.8(GND1)
GND_ISO: C28.2 R71.1 U1.9(GND2) U1.15(GND2) ; port GND_ISO
NetIC1_25: U1.6(TxD) ; port RS485_RX
NetIC1_26: U1.3(RxD) ; port RS485_TX
NetIC1_27: R72.2 U1.4(~{RE}) U1.5(DE) ; port R/D_Enable
NetR69_1: R69.1 R71.2 U1.13(B) ; port RS485_B
NetR69_2: R69.2 R70.1 U1.12(A) ; port RS485_A
NetR73_2: R73.2 U1.7(PV)

Not connected (* = marked no-connect by the designer): U1 10(NC)* 11(NC)* 14(NC)*

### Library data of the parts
C27 C28 = cap: Capacitor; Voltage: *V; Dielectric: *X5R; Tolerance: *%; OrderAdvanced: CERCAP *0603 0.1uF *X5R *%
R69 = Resistor: OrderAdvanced: RES *0603 120 *%; Tolerance: *%
R70 R71 = Resistor: OrderAdvanced: RES *0603 560 *%; Tolerance: *%
R72 R73 = Resistor: as R43 on sheet main

## Sheet MotorDriver.SchDoc
size A4; SheetNumber: 5; SheetTotal: 6
Used 8 times, as channels U_MotorDriver_1, U_MotorDriver_2, U_MotorDriver_3, U_MotorDriver_4, U_MotorDriver_5, U_MotorDriver_6, U_MotorDriver_7, U_MotorDriver_8. Parts and nets are listed once, with the designators drawn on the sheet.
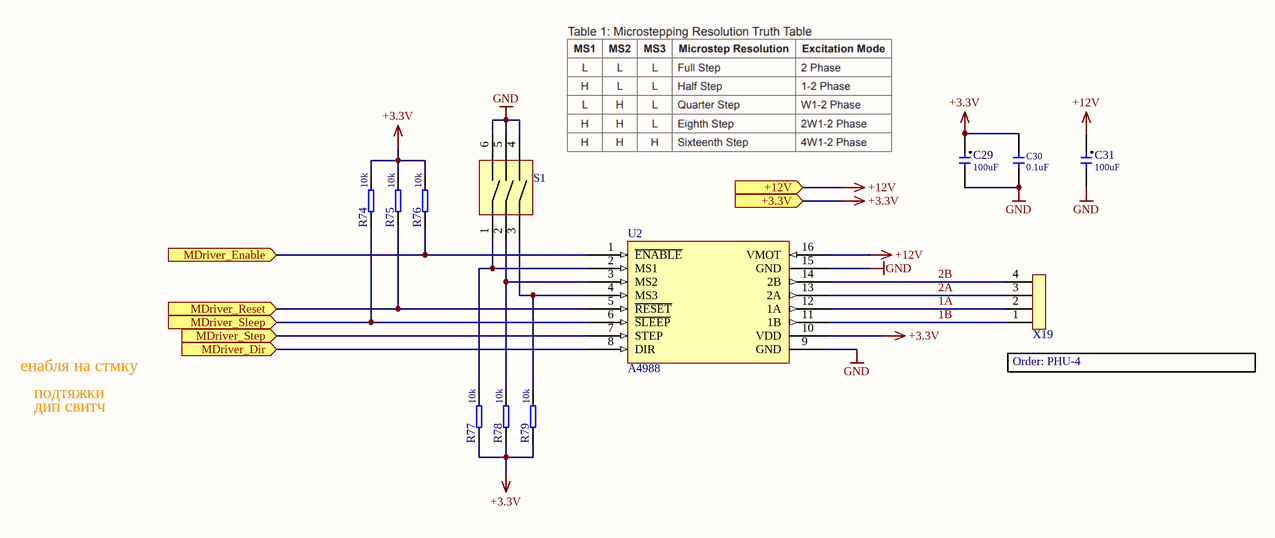
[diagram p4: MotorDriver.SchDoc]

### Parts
Additional_order3  Order: PHU-4  (hidden comment: Additional order)  (mechanical)
C29  100uF  [ECAP_SMD_0605]
C30  0.1uF  [CERCAP 0603]
C31  100uF  [ECAP_SMD_0810]
R74  10k  [RES 0603]
R75  10k  [RES 0603]
R76  10k  [RES 0603]
R77  10k  [RES 0603]
R78  10k  [RES 0603]
R79  10k  [RES 0603]
S1  DIP Switch5x  [DIP-6-SW]  (value not drawn)
U2  A4988  [A4988]
X19  Header  [PWL-4]  (value not drawn)

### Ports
+3.3V (in, see main[2B], Ethernet[2A], mcu[2A], Power[3C]), +12V (in, see main[2B], Power[3A]), MDriver_Dir (in, see main[2B]), MDriver_Enable (in, see main[2B]), MDriver_Reset (in, see main[2B]), MDriver_Sleep (in, see main[2B]), MDriver_Step (in, see main[2B])

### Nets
+3.3V: C29.1(+) C30.2 R74.2 R75.2 R76.2 R77.1 R78.1 R79.1 U2.10(VDD) ; port +3.3V
+12V: C31.1(+) U2.16(VMOT) ; port +12V
GND: C29.2(-) C30.1 C31.2(-) S1.4 S1.5 S1.6 U2.9(GND) U2.15(GND)
1A: U2.12(1A) X19.2
1B: U2.11(1B) X19.1
2A: U2.13(2A) X19.3
2B: U2.14(2B) X19.4
MDriver_Dir: U2.8(DIR) ; port MDriver_Dir
MDriver_Enable: R76.1 U2.1(~{ENABLE}) ; port MDriver_Enable
MDriver_Reset: R75.1 U2.5(~{RESET}) ; port MDriver_Reset
MDriver_Sleep: R74.1 U2.6(~{SLEEP}) ; port MDriver_Sleep
MDriver_Step: U2.7(STEP) ; port MDriver_Step
NetR77_2: R77.2 S1.1 U2.2(MS1)
NetR78_2: R78.2 S1.2 U2.3(MS2)
NetR79_2: R79.2 S1.3 U2.4(MS3)

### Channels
U_MotorDriver_1: designators Additional order3=Additional_order3_U_MotorDriver_1 C29=C29_U_MotorDriver_1 C30=C30_U_MotorDriver_1 C31=C31_U_MotorDriver_1 R74=R74_U_MotorDriver_1 R75=R75_U_MotorDriver_1 R76=R76_U_MotorDriver_1 R77=R77_U_MotorDriver_1 R78=R78_U_MotorDriver_1 R79=R79_U_MotorDriver_1 S1=S1_U_MotorDriver_1 U2=U2_U_MotorDriver_1 X19=X19_U_MotorDriver_1; ports +3.3V=+3.3V +12V=+12V MDriver_Dir=DRIVER_1_DIR MDriver_Enable=DRIVER_EN_Global MDriver_Reset=DRIVER_RES_Global MDriver_Sleep=DRIVER_SLEEP_Global MDriver_Step=DRIVER_1_STEP
U_MotorDriver_2: designators Additional order3=Additional_order3_U_MotorDriver_2 C29=C29_U_MotorDriver_2 C30=C30_U_MotorDriver_2 C31=C31_U_MotorDriver_2 R74=R74_U_MotorDriver_2 R75=R75_U_MotorDriver_2 R76=R76_U_MotorDriver_2 R77=R77_U_MotorDriver_2 R78=R78_U_MotorDriver_2 R79=R79_U_MotorDriver_2 S1=S1_U_MotorDriver_2 U2=U2_U_MotorDriver_2 X19=X19_U_MotorDriver_2; ports +3.3V=+3.3V +12V=+12V MDriver_Dir=DRIVER_2_DIR MDriver_Enable=DRIVER_EN_Global MDriver_Reset=DRIVER_RES_Global MDriver_Sleep=DRIVER_SLEEP_Global MDriver_Step=DRIVER_2_STEP
U_MotorDriver_3: designators Additional order3=Additional_order3_U_MotorDriver_3 C29=C29_U_MotorDriver_3 C30=C30_U_MotorDriver_3 C31=C31_U_MotorDriver_3 R74=R74_U_MotorDriver_3 R75=R75_U_MotorDriver_3 R76=R76_U_MotorDriver_3 R77=R77_U_MotorDriver_3 R78=R78_U_MotorDriver_3 R79=R79_U_MotorDriver_3 S1=S1_U_MotorDriver_3 U2=U2_U_MotorDriver_3 X19=X19_U_MotorDriver_3; ports +3.3V=+3.3V +12V=+12V MDriver_Dir=DRIVER_3_DIR MDriver_Enable=DRIVER_EN_Global MDriver_Reset=DRIVER_RES_Global MDriver_Sleep=DRIVER_SLEEP_Global MDriver_Step=DRIVER_3_STEP
U_MotorDriver_4: designators Additional order3=Additional_order3_U_MotorDriver_4 C29=C29_U_MotorDriver_4 C30=C30_U_MotorDriver_4 C31=C31_U_MotorDriver_4 R74=R74_U_MotorDriver_4 R75=R75_U_MotorDriver_4 R76=R76_U_MotorDriver_4 R77=R77_U_MotorDriver_4 R78=R78_U_MotorDriver_4 R79=R79_U_MotorDriver_4 S1=S1_U_MotorDriver_4 U2=U2_U_MotorDriver_4 X19=X19_U_MotorDriver_4; ports +3.3V=+3.3V +12V=+12V MDriver_Dir=DRIVER_4_DIR MDriver_Enable=DRIVER_EN_Global MDriver_Reset=DRIVER_RES_Global MDriver_Sleep=DRIVER_SLEEP_Global MDriver_Step=DRIVER_4_STEP
U_MotorDriver_5: designators Additional order3=Additional_order3_U_MotorDriver_5 C29=C29_U_MotorDriver_5 C30=C30_U_MotorDriver_5 C31=C31_U_MotorDriver_5 R74=R74_U_MotorDriver_5 R75=R75_U_MotorDriver_5 R76=R76_U_MotorDriver_5 R77=R77_U_MotorDriver_5 R78=R78_U_MotorDriver_5 R79=R79_U_MotorDriver_5 S1=S1_U_MotorDriver_5 U2=U2_U_MotorDriver_5 X19=X19_U_MotorDriver_5; ports +3.3V=+3.3V +12V=+12V MDriver_Dir=DRIVER_5_DIR MDriver_Enable=DRIVER_EN_Global MDriver_Reset=DRIVER_RES_Global MDriver_Sleep=DRIVER_SLEEP_Global MDriver_Step=DRIVER_5_STEP
U_MotorDriver_6: designators Additional order3=Additional_order3_U_MotorDriver_6 C29=C29_U_MotorDriver_6 C30=C30_U_MotorDriver_6 C31=C31_U_MotorDriver_6 R74=R74_U_MotorDriver_6 R75=R75_U_MotorDriver_6 R76=R76_U_MotorDriver_6 R77=R77_U_MotorDriver_6 R78=R78_U_MotorDriver_6 R79=R79_U_MotorDriver_6 S1=S1_U_MotorDriver_6 U2=U2_U_MotorDriver_6 X19=X19_U_MotorDriver_6; ports +3.3V=+3.3V +12V=+12V MDriver_Dir=DRIVER_6_DIR MDriver_Enable=DRIVER_EN_Global MDriver_Reset=DRIVER_RES_Global MDriver_Sleep=DRIVER_SLEEP_Global MDriver_Step=DRIVER_6_STEP
U_MotorDriver_7: designators Additional order3=Additional_order3_U_MotorDriver_7 C29=C29_U_MotorDriver_7 C30=C30_U_MotorDriver_7 C31=C31_U_MotorDriver_7 R74=R74_U_MotorDriver_7 R75=R75_U_MotorDriver_7 R76=R76_U_MotorDriver_7 R77=R77_U_MotorDriver_7 R78=R78_U_MotorDriver_7 R79=R79_U_MotorDriver_7 S1=S1_U_MotorDriver_7 U2=U2_U_MotorDriver_7 X19=X19_U_MotorDriver_7; ports +3.3V=+3.3V +12V=+12V MDriver_Dir=DRIVER_7_DIR MDriver_Enable=DRIVER_EN_Global MDriver_Reset=DRIVER_RES_Global MDriver_Sleep=DRIVER_SLEEP_Global MDriver_Step=DRIVER_7_STEP
U_MotorDriver_8: designators Additional order3=Additional_order3_U_MotorDriver_8 C29=C29_U_MotorDriver_8 C30=C30_U_MotorDriver_8 C31=C31_U_MotorDriver_8 R74=R74_U_MotorDriver_8 R75=R75_U_MotorDriver_8 R76=R76_U_MotorDriver_8 R77=R77_U_MotorDriver_8 R78=R78_U_MotorDriver_8 R79=R79_U_MotorDriver_8 S1=S1_U_MotorDriver_8 U2=U2_U_MotorDriver_8 X19=X19_U_MotorDriver_8; ports +3.3V=+3.3V +12V=+12V MDriver_Dir=DRIVER_8_DIR MDriver_Enable=DRIVER_EN_Global MDriver_Reset=DRIVER_RES_Global MDriver_Sleep=DRIVER_SLEEP_Global MDriver_Step=DRIVER_8_STEP

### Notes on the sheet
- енабля на стмку
- подтяжки
- дип свитч

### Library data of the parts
Additional_order3 = Additional_Order
C29 = capp: Capacitor; Voltage: *V; OrderAdvanced: TECAP *case A 100uF *%; Tolerance: *%
C30 = cap: as C27 on sheet UART-RS485
C31 = capp: Capacitor; Voltage: 25V; OrderAdvanced: TECAP *case A 100uF *%; Tolerance: *%
R74-R79 = Resistor: as R43 on sheet main
S1 = DIP_Switch3x: Switcher; Order: DS1040-03RN; OriginalSource: AltTab
U2 = A4988: STEPPER DRIVER
X19 = Header 4x1: 4x1 header; System: Connector; OriginalSource: AltTab

## Sheet Power.SchDoc
size A4; SheetNumber: 6; SheetTotal: 6
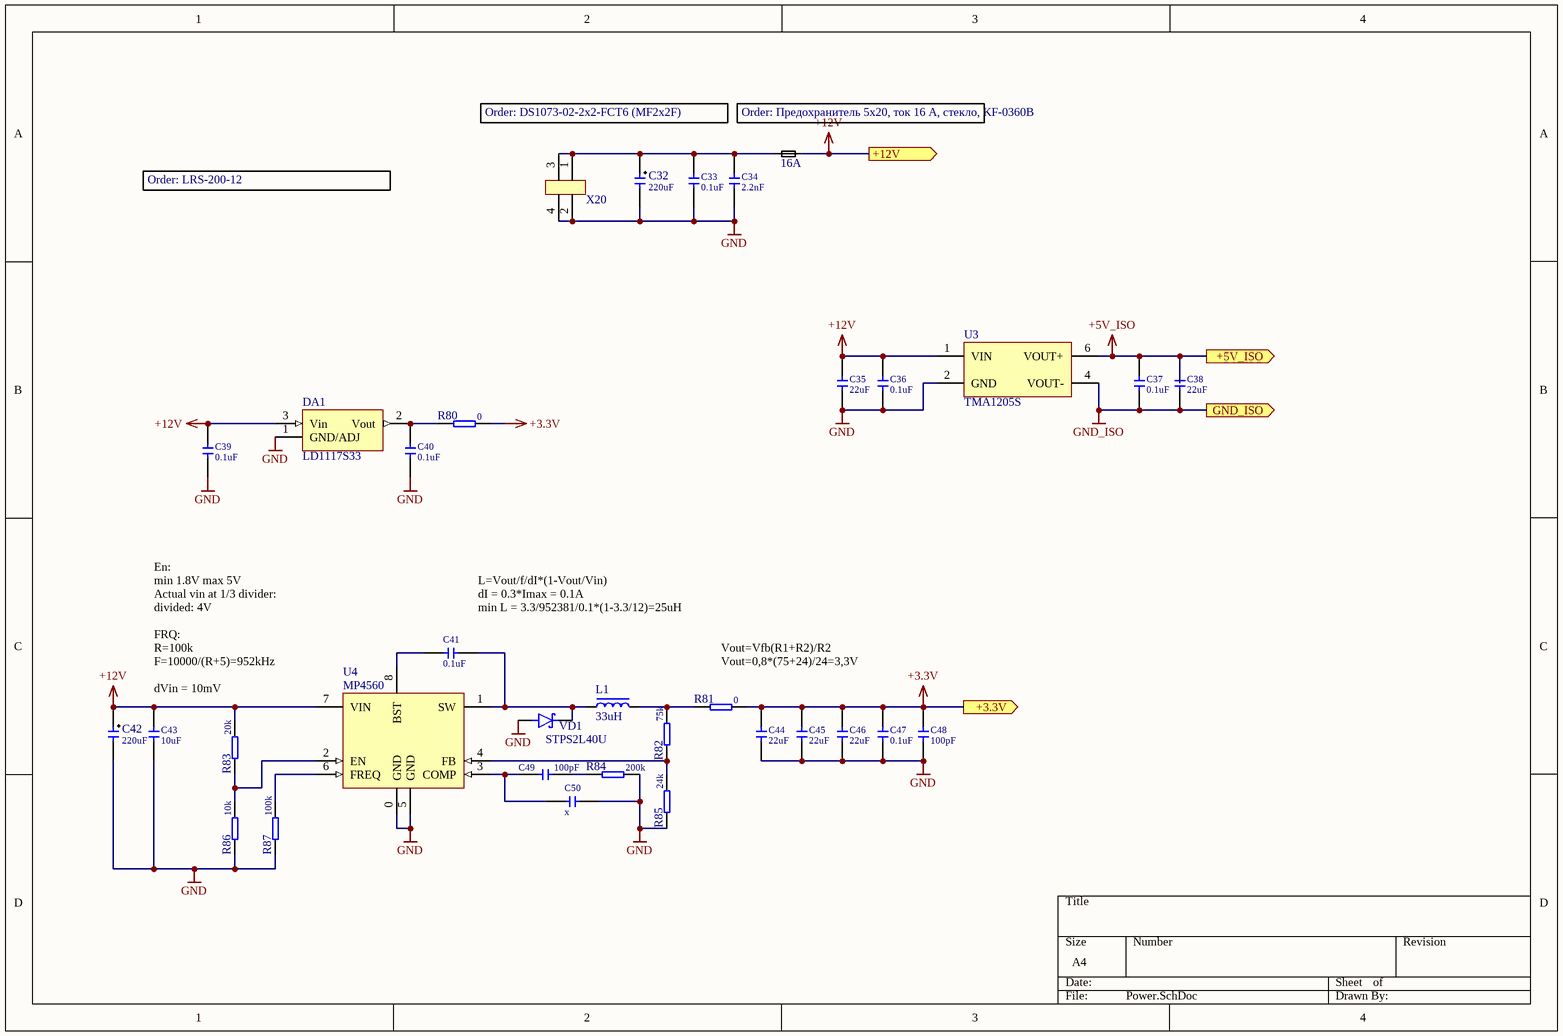
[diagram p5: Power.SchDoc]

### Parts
Additional_order1  Order: LRS-200-12  (hidden comment: Additional order)  (mechanical)
Additional_order4  Order: DS1073-02-2x2-FСT6 (MF2x2F)  (hidden comment: Additional order)  (mechanical)
Additional_order5  Order: Предохранитель 5x20, ток 16 А, стекло, KF-0360B  (hidden comment: Additional order)  (mechanical)
C32  220uF  [ECAP_SMD_0810]
C33  0.1uF  [CERCAP 0603]
C34  2.2nF  [CERCAP 0603]
C35  22uF  [CERCAP 0603]
C36  0.1uF  [CERCAP 0603]
C37  0.1uF  [CERCAP 0603]
C38  22uF  [CERCAP 0603]
C39  0.1uF  [CERCAP 0603]
C40  0.1uF  [CERCAP 0603]
C41  0.1uF  [CERCAP 0603]
C42  220uF  [ECAP_SMD_0810]
C43  10uF  [CERCAP 0603]
C44  22uF  [CERCAP 0603]
C45  22uF  [CERCAP 0603]
C46  22uF  [CERCAP 0603]
C47  0.1uF  [CERCAP 0603]
C48  100pF  [CERCAP 0603]
C49  100pF  [CERCAP 0603]
C50  x  [CERCAP 0603]
DA1  LD1117S33  [SOT223]
FU1  16A  [Fuse Holder 20x5mm]
L1  33uH  [CDRH8D43NP-330NC]
R80  0  [RES 0603]
R81  0  [RES 0603]
R82  75k  [RES 0603]
R83  20k  [RES 0603]
R84  200k  [RES 0603]
R85  24k  [RES 0603]
R86  10k  [RES 0603]
R87  100k  [RES 0603]
U3  TMA1205S  [SIP5]
U4  MP4560  [SO-8 PowerPad]
VD1  STPS2L40U  [DO-214AC(SMA)]
X20  Header  [MF-2x2 MRA]  (value not drawn)

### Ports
+3.3V (out, see main[4A], Ethernet[2A], mcu[2A], MotorDriver[3B]), +5V_ISO (out, see main[4A], UART-RS485[2B]), +12V (out, see main[4A], MotorDriver[3B]), GND_ISO (out, see main[4A], UART-RS485[2B])

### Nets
+3.3V: C44.2 C45.2 C46.2 C47.2 C48.2 R80.2 R81.2 ; port +3.3V
+5V_ISO: C37.2 C38.2 U3.6(VOUT+) ; port +5V_ISO
+12V: C35.2 C36.2 C39.2 C42.1(+) C43.2 DA1.3(Vin) FU1.2 R83.2 U3.1(VIN) U4.7(VIN) ; port +12V
GND: C32.2(-) C33.1 C34.1 C35.1 C36.1 C39.1 C40.1 C42.2(-) C43.1 C44.1 C45.1 C46.1 C47.1 C48.1 C50.2 DA1.1(GND/ADJ) R84.2 R85.1 R86.1 R87.1 U3.2(GND) U4.0(GND) U4.5(GND) VD1.A(Anode) X20.2 X20.4
GND_ISO: C37.1 C38.1 U3.4(VOUT-) ; port GND_ISO
NetC32_1: C32.1(+) C33.2 C34.2 FU1.1 X20.1 X20.3
NetC40_2: C40.2 DA1.2(Vout) R80.1
NetC41_1: C41.1 U4.8(BST)
NetC41_2: C41.2 L1.1 U4.1(SW) VD1.C(Cathode)
NetC49_1: C49.1 C50.1 U4.3(COMP)
NetC49_2: C49.2 R84.1
NetL1_2: L1.2 R81.1 R82.2
NetR82_1: R82.1 R85.2 U4.4(FB)
NetR83_1: R83.1 R86.2 U4.2(EN)
NetR87_2: R87.2 U4.6(FREQ)

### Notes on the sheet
- (near C41) L=Vout/f/dI*(1-Vout/Vin)
  dI = 0.3*Imax = 0.1A
  min L = 3.3/952381/0.1*(1-3.3/12)=25uH
- En:
  min 1.8V max 5V
  Actual vin at 1/3 divider:
  divided: 4V
  FRQ:
  R=100k
  F=10000/(R+5)=952kHz
  dVin = 10mV
- (near R81) Vout=Vfb(R1+R2)/R2
  Vout=0,8*(75+24)/24=3,3V

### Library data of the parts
Additional_order1 Additional_order4 Additional_order5 = Additional_Order
C32 = capp: Capacitor; Voltage: 25V; OrderAdvanced: TECAP *case A 220uF *%; Tolerance: *%
C33 C36 C39 C41 = cap: Capacitor; Voltage: 25V; Dielectric: *X5R; Tolerance: *%; OrderAdvanced: CERCAP *0603 0.1uF *X5R *%
C34 = cap: Capacitor; Voltage: 25V; Dielectric: *X5R; Tolerance: *%; OrderAdvanced: CERCAP *0603 2.2nF *X5R *%
C35 = cap: Capacitor; Voltage: 25V; Dielectric: *X5R; Tolerance: *%; OrderAdvanced: CERCAP *0603 22uF *X5R *%
C37 C47 = cap: as C7 on sheet Ethernet
C38 C44-C46 = cap: Capacitor; Voltage: 10V; Dielectric: *X5R; Tolerance: *%; OrderAdvanced: CERCAP *0603 22uF *X5R *%
C40 = cap: as C27 on sheet UART-RS485
C42 = capp: Capacitor; Order: ECAP SMD, 220 мкФ, 25 В, 105°C, 20% 8x10.5мм; Voltage: 25V; OrderAdvanced: TECAP *case A 220uF *%; Tolerance: *%
C43 = cap: Capacitor; Voltage: 25V; Dielectric: *X5R; Tolerance: *%; OrderAdvanced: CERCAP *0603 10uF *X5R *%
C48 = cap: Capacitor; Voltage: 10V; Dielectric: *X5R; Tolerance: *%; OrderAdvanced: CERCAP *0603 100pF *X5R *%
C49 = cap: Capacitor; Voltage: 25V; Dielectric: *X5R; Tolerance: *%; OrderAdvanced: CERCAP *0603 100pF *X5R *%
C50 = cap: Capacitor; Voltage: *V; Dielectric: *X5R; Tolerance: *%; OrderAdvanced: CERCAP *0603 x *X5R *%
DA1 = LD1117S33: LDO 3.3V; Original Source: AltTabLibrary
FU1 = Fuse: Over current protect; Order: FH-102
L1 = Inductor
R80 R81 = Resistor: as R28 on sheet Ethernet
R82 = Resistor: OrderAdvanced: RES *0603 75k *%; Tolerance: *%
R83 = Resistor: as R90 on sheet main
R84 = Resistor: as R45 on sheet main
R85 = Resistor: OrderAdvanced: RES *0603 24k *%; Tolerance: *%
R86 = Resistor: as R43 on sheet main
R87 = Resistor: as R68 on sheet mcu
U3 = TMA0505S: Преобразователь DC-DC на печатную плату
U4 = MP4560: 2A, 2MHz, 55V Step-Down Converter; Order: MP4560DN-LF-Z
VD1 = DiodeS: Diode Shottky; ForwardCurrent: 2A; ForwardVoltage: *V; ReverseCurrent: *A; ReverseVoltage: 40V; OriginalSource: AltTab
X20 = Header 2x2: 2x2 header; Order: MF-2x2MRA; System: Connector; OriginalSource: AltTab

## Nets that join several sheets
+3.3V: main (14 pins), mcu (5 pins), Ethernet (11 pins), UART-RS485 (C27.2 R73.1 U1.1), U_MotorDriver_1 (9 pins), Power (7 pins), U_MotorDriver_2 (9 pins), U_MotorDriver_3 (9 pins), U_MotorDriver_4 (9 pins), U_MotorDriver_5 (9 pins), U_MotorDriver_6 (9 pins), U_MotorDriver_7 (9 pins), U_MotorDriver_8 (9 pins)
+5V_ISO: main (LED3.1), UART-RS485 (C28.1 R70.2 U1.16), Power (C37.2 C38.2 U3.6)
+12V: main (LED4.1), U_MotorDriver_1 (C31_U_MotorDriver_1.1 U2_U_MotorDriver_1.16), Power (10 pins), U_MotorDriver_2 (C31_U_MotorDriver_2.1 U2_U_MotorDriver_2.16), U_MotorDriver_3 (C31_U_MotorDriver_3.1 U2_U_MotorDriver_3.16), U_MotorDriver_4 (C31_U_MotorDriver_4.1 U2_U_MotorDriver_4.16), U_MotorDriver_5 (C31_U_MotorDriver_5.1 U2_U_MotorDriver_5.16), U_MotorDriver_6 (C31_U_MotorDriver_6.1 U2_U_MotorDriver_6.16), U_MotorDriver_7 (C31_U_MotorDriver_7.1 U2_U_MotorDriver_7.16), U_MotorDriver_8 (C31_U_MotorDriver_8.1 U2_U_MotorDriver_8.16)
GND: main (30 pins), mcu (7 pins), Ethernet (23 pins), UART-RS485 (C27.1 R72.1 U1.2 U1.8), U_MotorDriver_1 (8 pins), Power (26 pins), U_MotorDriver_2 (8 pins), U_MotorDriver_3 (8 pins), U_MotorDriver_4 (8 pins), U_MotorDriver_5 (8 pins), U_MotorDriver_6 (8 pins), U_MotorDriver_7 (8 pins), U_MotorDriver_8 (8 pins)
GND_ISO: main (R90.2), UART-RS485 (C28.2 R71.1 U1.9 U1.15), Power (C37.1 C38.1 U3.4)
DRIVER_1_DIR: mcu (R67.2), U_MotorDriver_1 (U2_U_MotorDriver_1.8)
DRIVER_1_STEP: mcu (R50.1), U_MotorDriver_1 (U2_U_MotorDriver_1.7)
DRIVER_2_DIR: mcu (R65.2), U_MotorDriver_2 (U2_U_MotorDriver_2.8)
DRIVER_2_STEP: mcu (R66.2), U_MotorDriver_2 (U2_U_MotorDriver_2.7)
DRIVER_3_DIR: mcu (R61.2), U_MotorDriver_3 (U2_U_MotorDriver_3.8)
DRIVER_3_STEP: mcu (R63.2), U_MotorDriver_3 (U2_U_MotorDriver_3.7)
DRIVER_4_DIR: mcu (R57.2), U_MotorDriver_4 (U2_U_MotorDriver_4.8)
DRIVER_4_STEP: mcu (R59.2), U_MotorDriver_4 (U2_U_MotorDriver_4.7)
DRIVER_5_DIR: mcu (R62.1), U_MotorDriver_5 (U2_U_MotorDriver_5.8)
DRIVER_5_STEP: mcu (R64.1), U_MotorDriver_5 (U2_U_MotorDriver_5.7)
DRIVER_6_DIR: mcu (R58.1), U_MotorDriver_6 (U2_U_MotorDriver_6.8)
DRIVER_6_STEP: mcu (R60.1), U_MotorDriver_6 (U2_U_MotorDriver_6.7)
DRIVER_7_DIR: mcu (R55.1), U_MotorDriver_7 (U2_U_MotorDriver_7.8)
DRIVER_7_STEP: mcu (R56.1), U_MotorDriver_7 (U2_U_MotorDriver_7.7)
DRIVER_8_DIR: mcu (R49.1), U_MotorDriver_8 (U2_U_MotorDriver_8.8)
DRIVER_8_STEP: mcu (R54.1), U_MotorDriver_8 (U2_U_MotorDriver_8.7)
DRIVER_EN_Global: mcu (R53.1), U_MotorDriver_1 (R76_U_MotorDriver_1.1 U2_U_MotorDriver_1.1), U_MotorDriver_2 (R76_U_MotorDriver_2.1 U2_U_MotorDriver_2.1), U_MotorDriver_3 (R76_U_MotorDriver_3.1 U2_U_MotorDriver_3.1), U_MotorDriver_4 (R76_U_MotorDriver_4.1 U2_U_MotorDriver_4.1), U_MotorDriver_5 (R76_U_MotorDriver_5.1 U2_U_MotorDriver_5.1), U_MotorDriver_6 (R76_U_MotorDriver_6.1 U2_U_MotorDriver_6.1), U_MotorDriver_7 (R76_U_MotorDriver_7.1 U2_U_MotorDriver_7.1), U_MotorDriver_8 (R76_U_MotorDriver_8.1 U2_U_MotorDriver_8.1)
DRIVER_RES_Global: mcu (R52.1), U_MotorDriver_1 (R75_U_MotorDriver_1.1 U2_U_MotorDriver_1.5), U_MotorDriver_2 (R75_U_MotorDriver_2.1 U2_U_MotorDriver_2.5), U_MotorDriver_3 (R75_U_MotorDriver_3.1 U2_U_MotorDriver_3.5), U_MotorDriver_4 (R75_U_MotorDriver_4.1 U2_U_MotorDriver_4.5), U_MotorDriver_5 (R75_U_MotorDriver_5.1 U2_U_MotorDriver_5.5), U_MotorDriver_6 (R75_U_MotorDriver_6.1 U2_U_MotorDriver_6.5), U_MotorDriver_7 (R75_U_MotorDriver_7.1 U2_U_MotorDriver_7.5), U_MotorDriver_8 (R75_U_MotorDriver_8.1 U2_U_MotorDriver_8.5)
DRIVER_SLEEP_Global: mcu (R51.1), U_MotorDriver_1 (R74_U_MotorDriver_1.1 U2_U_MotorDriver_1.6), U_MotorDriver_2 (R74_U_MotorDriver_2.1 U2_U_MotorDriver_2.6), U_MotorDriver_3 (R74_U_MotorDriver_3.1 U2_U_MotorDriver_3.6), U_MotorDriver_4 (R74_U_MotorDriver_4.1 U2_U_MotorDriver_4.6), U_MotorDriver_5 (R74_U_MotorDriver_5.1 U2_U_MotorDriver_5.6), U_MotorDriver_6 (R74_U_MotorDriver_6.1 U2_U_MotorDriver_6.6), U_MotorDriver_7 (R74_U_MotorDriver_7.1 U2_U_MotorDriver_7.6), U_MotorDriver_8 (R74_U_MotorDriver_8.1 U2_U_MotorDriver_8.6)
ENDSW_1: main (C1.1 R4.2 R5.1), mcu (IC1.44)
ENDSW_2: main (C2.1 R6.2 R7.1), mcu (IC1.42)
ENDSW_3: main (C3.1 R8.2 R12.1), mcu (IC1.43)
ENDSW_4: main (C4.1 R14.2 R19.1), mcu (IC1.41)
ENDSW_5: main (C5.1 R20.2 R21.1), mcu (IC1.39)
ENDSW_6: main (C6.1 R29.2 R30.1), mcu (IC1.40)
ENDSW_7: main (C18.1 R31.2 R32.1), mcu (IC1.37)
ENDSW_8: main (C19.1 R33.2 R34.1), mcu (IC1.38)
ENDSW_9: main (C20.1 R35.2 R36.1), mcu (IC1.36)
ENDSW_10: main (C21.1 R37.2 R38.1), mcu (IC1.35)
ENDSW_11: main (C22.1 R39.2 R40.1), mcu (IC1.34)
ENDSW_12: main (C23.1 R41.2 R42.1), mcu (IC1.33)
ETH_CS: mcu (IC1.21), Ethernet (R16.1)
ETH_INT: mcu (IC1.22), Ethernet (R24.1)
ETH_MISO: mcu (IC1.23), Ethernet (R18.1)
ETH_MOSI: mcu (IC1.19), Ethernet (R17.1)
ETH_Reset: mcu (IC1.20), Ethernet (R15.1)
ETH_SCK: mcu (IC1.18), Ethernet (R22.1)
NetIC1_25: mcu (IC1.25), UART-RS485 (U1.6)
NetIC1_26: mcu (IC1.26), UART-RS485 (U1.3)
NetIC1_27: mcu (IC1.27), UART-RS485 (R72.2 U1.4 U1.5)
NetR69_1: main (X2.2), UART-RS485 (R69.1 R71.2 U1.13)
NetR69_2: main (X2.1), UART-RS485 (R69.2 R70.1 U1.12)
Probe_1: main (R44.2 R45.1), mcu (IC1.30)
Probe_1_PWR: main (R43.2), mcu (IC1.13)
Probe_2: main (R47.2 R48.1), mcu (IC1.31)
Probe_2_PWR: main (R46.2), mcu (IC1.14)
RESET: main (R3.2), mcu (IC1.12 R68.2 X18.2)
SWCLK: main (R1.2), mcu (IC1.46)
SWDIO: main (R2.2), mcu (IC1.45)
USER_ДУВ: main (LED2.1), mcu (IC1.29)

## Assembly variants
Test: all parts fitted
